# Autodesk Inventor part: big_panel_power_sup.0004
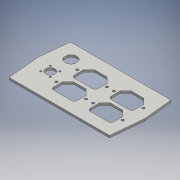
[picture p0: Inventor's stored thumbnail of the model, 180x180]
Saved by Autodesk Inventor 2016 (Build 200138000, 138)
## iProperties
Created: 2016-12
Part Number: big_panel_power_sup.0004
Material: Типовые
Document SubType Name: Modeling
Designer: admin
Density: 1 g/cm^3
Appearance: По умолчанию
Author: admin
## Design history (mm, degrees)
sketch "Эскиз1"
  geometry: L1 (-68, -41.5)-(68, -41.5); L2 (68, 41.5)-(-68, 41.5); L3 (-68, 41.5)-(-72, 2); L4 (-72, 2)-(-68, -41.5); L5 (68, 41.5)-(72, 2); L6 (72, 2)-(68, -41.5); 2 further points
  constraints: 12 end point, 1 horizontal, 1 midpoint, 1 parallel, 1 vertical alignment
extrude "Выдавливание1" new body sketch "Эскиз1" distance "d20" = 3; taper "d21" = 0 deg
sketch "Эскиз4"
  geometry: L1 (30.426, -2.9)-(47.426, -2.9); L2 (54.926, -10.4)-(54.926, -22.5); L3 (50.926, -26.5)-(26.926, -26.5); L4 (22.926, -22.5)-(22.926, -10.4); L5 (22.926, -2.9)-(54.926, -26.5); L6 (22.926, -26.5)-(54.926, -2.9); L7 (14.176, -28.75)-(63.676, -28.75); L8 (63.676, -28.75)-(63.676, -0.65); L9 (63.676, -0.65)-(14.176, -0.65); L10 (14.176, -0.65)-(14.176, -28.75); L11 (14.176, -28.75)-(63.676, -0.65); L12 (63.676, -28.75)-(14.176, -0.65); L13 (22.926, -10.4)-(30.426, -2.9); L14 (54.926, -10.4)-(47.426, -2.9); L15 (30.426, 25.3)-(47.426, 25.3); L16 (50.926, 1.7)-(26.926, 1.7); L17 (22.926, 25.3)-(54.926, 1.7); L18 (22.926, 1.7)-(54.926, 25.3); L19 (14.176, -0.55)-(63.676, -0.55); L20 (63.676, -0.55)-(14.176, 27.55); L21 (14.176, -0.55)-(63.676, 27.55); L22 (63.676, 27.55)-(14.176, 27.55); L23 (22.926, 17.8)-(30.426, 25.3); L24 (22.926, 5.7)-(22.926, 17.8); L25 (14.176, 27.55)-(14.176, -0.55); L26 (54.926, 17.8)-(54.926, 5.7); L27 (54.926, 17.8)-(47.426, 25.3); L28 (63.676, -0.55)-(63.676, 27.55); L29 (-19.174, 25.3)-(-2.174, 25.3); L30 (1.326, 1.7)-(-22.674, 1.7); L31 (-26.674, 25.3)-(5.326, 1.7); L32 (-26.674, 1.7)-(5.326, 25.3); L33 (-35.424, -0.55)-(14.076, -0.55); L34 (14.076, -0.55)-(-35.424, 27.55); L35 (-35.424, -0.55)-(14.076, 27.55); L36 (14.076, 27.55)-(-35.424, 27.55); L37 (-26.674, 17.8)-(-19.174, 25.3); L38 (-26.674, 5.7)-(-26.674, 17.8); L39 (-35.424, 27.55)-(-35.424, -0.55); L40 (5.326, 17.8)-(5.326, 5.7); L41 (5.326, 17.8)-(-2.174, 25.3); L42 (14.076, -0.55)-(14.076, 27.55); L43 (-19.174, -2.9)-(-2.174, -2.9); L44 (1.326, -26.5)-(-22.674, -26.5); L45 (-26.674, -2.9)-(5.326, -26.5); L46 (-26.674, -26.5)-(5.326, -2.9); L47 (-35.424, -28.75)-(14.076, -28.75); L48 (14.076, -28.75)-(-35.424, -0.65); L49 (-35.424, -28.75)-(14.076, -0.65); L50 (14.076, -0.65)-(-35.424, -0.65); L51 (-26.674, -10.4)-(-19.174, -2.9); L52 (-26.674, -22.5)-(-26.674, -10.4); L53 (-35.424, -0.65)-(-35.424, -28.75); L54 (5.326, -10.4)-(5.326, -22.5); L55 (5.326, -10.4)-(-2.174, -2.9); L56 (14.076, -28.75)-(14.076, -0.65); L57 (-56.279, -15.5)-(-38.279, -15.5); L58 (-38.279, -15.5)-(-38.279, 2.5); L59 (-38.279, 2.5)-(-56.279, 2.5); L60 (-56.279, 2.5)-(-56.279, -15.5); L61 (-56.279, -15.5)-(-38.279, 2.5); L62 (-38.279, -15.5)-(-56.279, 2.5); L63 (-53.779, -13)-(-40.779, -13); L64 (-40.779, -13)-(-40.779, 0)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; C1 r 1.25 at (-53.779, 0); C2 r 1.25 at (-40.779, 0); C3 r 1.25 at (-53.779, -13); C4 r 1.25 at (-40.779, -13); C5 r 6.25 at (-47.279, -6.5); C6 r 10.5 at (-47.279, 21.5); C7 r 1.75 at (-30.674, 13.5); C8 r 1.75 at (9.326, 13.5); C9 r 1.75 at (-30.674, -14.7); C10 r 1.75 at (9.326, -14.7); C11 r 1.75 at (18.926, 13.5); C12 r 1.75 at (58.926, 13.5); C13 r 1.75 at (18.926, -14.7); C14 r 1.75 at (58.926, -14.7); A1 r 4 centre (26.926, -22.5) between (22.926, -22.5) and (26.926, -26.5); A2 r 4 centre (50.926, -22.5) between (50.926, -26.5) and (54.926, -22.5); A3 r 4 centre (26.926, 5.7) between (22.926, 5.7) and (26.926, 1.7); A4 r 4 centre (50.926, 5.7) between (50.926, 1.7) and (54.926, 5.7); A5 r 4 centre (-22.674, 5.7) between (-26.674, 5.7) and (-22.674, 1.7); A6 r 4 centre (1.326, 5.7) between (1.326, 1.7) and (5.326, 5.7); A7 r 4 centre (-22.674, -22.5) between (-26.674, -22.5) and (-22.674, -26.5); A8 r 4 centre (1.326, -22.5) between (1.326, -26.5) and (5.326, -22.5); A9 r 7.8 centre (-47.279, 21.5) between (-54.629, 18.889) and (-39.929, 18.889); A10 r 7.8 centre (-47.279, 21.5) between (-39.929, 24.111) and (-54.629, 24.111); 17 further points
  constraints: 164 end point, 34 point on line, 26 midpoint, 24 centre point, 22 parallel, 20 point on circle, 17 horizontal, 16 tangent, 12 coincident, 11 perpendicular, 4 equal radius, 3 vertical, 1 horizontal alignment
  dimensions: "d56" = 49.5 distance of L9.end L8.end; "d57" = 28.1 distance of L8.end L7.end; "d58" = 32 distance of L5.start L6.end; "d59" = 23.6 distance of L6.end L5.end; "d60" = 7.5 distance of L4.end L5.start; "d61" = 7.5 distance of L1.start L5.start (= d60); "d62" = 7.5 distance of L2.start L6.end; "d63" = 7.5 distance of L1.end L6.end (= d62); "d64" = 4 radius of A1; "d65" = 49.5 distance of L20.end L21.end; "d66" = 28.1 distance of L21.end L19.end; "d67" = 32 distance of L17.start L18.end; "d68" = 23.6 distance of L18.end L17.end; "d69" = 7.5 distance of L23.start L17.start; "d70" = 7.5 distance of L15.start L17.start (= d69); "d71" = 7.5 distance of L26.start L18.end; "d72" = 7.5 distance of L15.end L18.end (= d71); "d73" = 4 radius of A3; "d74" = 49.5 distance of L34.end L35.end; "d75" = 28.1 distance of L35.end L33.end; "d76" = 32 distance of L31.start L32.end; "d77" = 23.6 distance of L32.end L31.end; "d78" = 7.5 distance of L37.start L31.start; "d79" = 7.5 distance of L29.start L31.start (= d78); "d80" = 7.5 distance of L40.start L32.end; "d81" = 7.5 distance of L29.end L32.end (= d80); "d82" = 4 radius of A5; "d83" = 49.5 distance of L48.end L49.end; "d84" = 28.1 distance of L49.end L47.end; "d85" = 32 distance of L45.start L46.end; "d86" = 23.6 distance of L46.end L45.end; "d87" = 7.5 distance of L51.start L45.start; "d88" = 7.5 distance of L43.start L45.start (= d87); "d89" = 7.5 distance of L54.start L46.end; "d90" = 7.5 distance of L43.end L46.end (= d89); "d91" = 4 radius of A7; "d92" = 18 distance of L59.end L58.end; "d93" = 18 distance of L58.end L57.end; "d94" = 13 distance of L65.end L64.end; "d95" = 13 distance of L64.end L63.end; "d96" = 2.5 diameter of C1; "d97" = 2.5 diameter of C2; "d98" = 2.5 diameter of C3; "d99" = 2.5 diameter of C4; "d100" = 12.5 diameter of C5; "d104" = 7.8 radius of A10; "d105" = 7.8 radius of A9; "d106" = 14.7 distance between parallel lines of L69 L70; "d107" = 5.22207 distance of L69.start L69.end; "d108" = 21 diameter of C6; "d109" = 17 distance of L75.start L75.end; "d110" = 17 distance of L76.start L76.end; "d111" = 15 distance between parallel lines of L3 L81; "d112" = 0.1 distance between parallel lines of L19 L9; "d113" = 0.1 distance between parallel lines of L10 L56; "d114" = 0.1 distance between parallel lines of L50 L33; "d116" = 35 distance from line of point (-47.279, -6.5) L81; "d117" = 20 distance from line of C6.centre L82; "d118" = 3.5 diameter of C7; "d119" = 3.5 diameter of C8; "d120" = 40 distance of L83.end L83.start; "d121" = 3.5 diameter of C9; "d122" = 3.5 diameter of C10; "d123" = 40 distance of L84.end L84.start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
extrude "Выдавливание4" cut sketch "Эскиз4" distance "d130" = 10; taper "d131" = 0 deg
node "Твердое тело1"
other parameters: "d34" = 77
